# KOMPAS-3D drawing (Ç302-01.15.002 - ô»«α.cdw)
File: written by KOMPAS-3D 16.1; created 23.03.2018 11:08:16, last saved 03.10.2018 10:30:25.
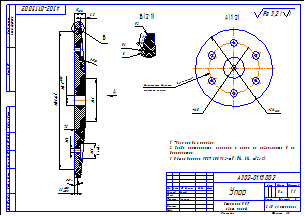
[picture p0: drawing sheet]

Sheet 1: A3, landscape

Title block, sheet 1: name: Упор; designation: А302-01.15.002; mass: 0,4; scale: 1:1; sheets: 1; organisation: ЗАО «Астерион»; sheet format: A3; stored path: \\192.168.87.28\Konstructor_doc\Мембранные насосы\Мембранный электропривод\А302-00.00.000 - ASTRA-302 (МЭ200)\Чертежи\А302-00.15.002 - Упор.cdw; drawn by: Милов; technical control: Лучихин

Views: Вид 1, Местный разрез 1, Спереди, Вид по стрелке 2, Выносной элемент 3, Выносной элемент Б, Выносной элемент
Referenced files in Z:\Мембранные насосы\Мембранный электропривод\А302-00.00.000 - ASTRA-302 (МЭ200)\3Д ПВХ\: А302-01.15.002 - Упор.m3d
Referenced files in Z:\Мембранные насосы\Мембранный электропривод\А302-00.00.000 - ASTRA-302 (МЭ200)\3Д\: А302-00.15.002 - Упор.m3d
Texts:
  Стержень ПВХ
  цвет серый
  допускается диаметр
  очертить резцом
  для разметки
  Ra 0,80
  *Размеры для справок.
  Следы инструмента, царапины и риски на поверхности  В  не
  допускаются.
  Общие допуски ГОСТ 30893.2-mK (H14, h14,  t2/2).
  Ra 3,2
  Ra 3,2 ( )
Dimensions and other numbers on the sheet: 13,5; 60; 190±0,1; 3,2; 5,6; 20; 6 отв.; 7,5; 15; 4 50'; 6,5; 214; 140; 6; 2; 1:1; 1; 0,4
